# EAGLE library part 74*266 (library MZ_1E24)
Quadruple EXCLUSIVE-NOR (XNOR), open-collector
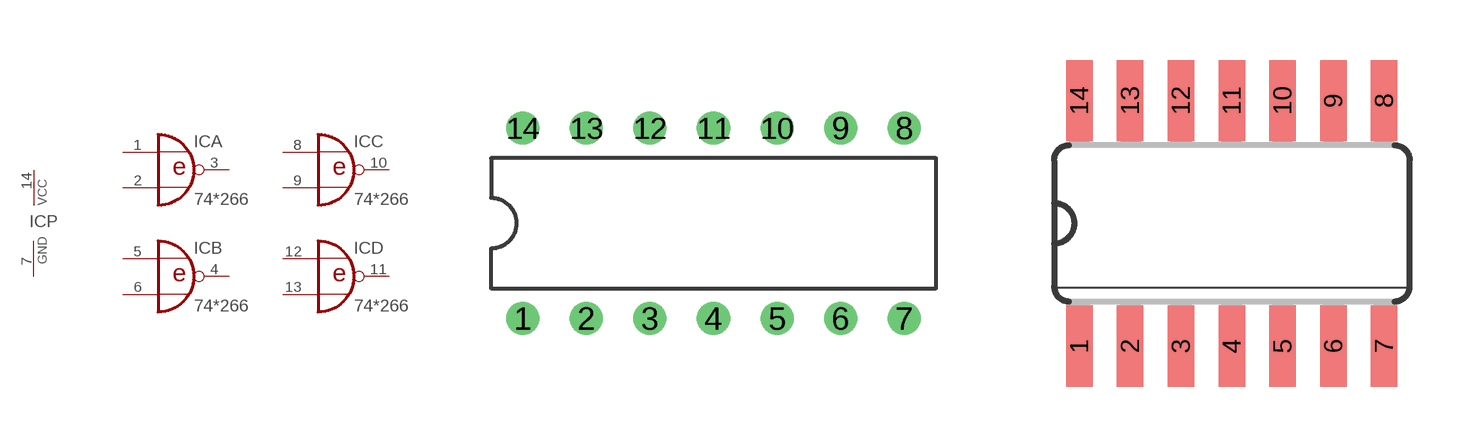
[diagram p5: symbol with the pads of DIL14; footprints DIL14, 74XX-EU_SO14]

Designator prefix IC; gates A=EU_74266 B=EU_74266 C=EU_74266 D=EU_74266 P=EU_PWRN

## 74266  [DIL14]
1  A:I0  in
2  A:I1  in
3  A:O  oc
4  B:O  oc
5  B:I0  in
6  B:I1  in
7  P:GND  pwr
8  C:I0  in
9  C:I1  in
10  C:O  oc
11  D:O  oc
12  D:I0  in
13  D:I1  in
14  P:VCC  pwr

## 74266D, 74HC266D  [74XX-EU_SO14]
Pads as for DIL14

## 74266FK, 74HC266FK, 74LS266FK  [74XX-EU_LCC20]
2  A:I0  in
3  A:I1  in
4  A:O  oc
6  B:O  oc
8  B:I0  in
9  B:I1  in
10  P:GND  pwr
12  C:I0  in
13  C:I1  in
14  C:O  oc
16  D:O  oc
18  D:I0  in
19  D:I1  in
20  P:VCC  pwr

## Footprint DIL14 (pad centres in mm)
Dual In Line Package
drill 0.813 round: 1 -7.62,-3.81; 2 -5.08,-3.81; 3 -2.54,-3.81; 4 0,-3.81; 5 2.54,-3.81; 6 5.08,-3.81; 7 7.62,-3.81; 8 7.62,3.81; 9 5.08,3.81; 10 2.54,3.81; 11 0,3.81; 12 -2.54,3.81; 13 -5.08,3.81; 14 -7.62,3.81

## Footprint 74XX-EU_SO14 (pad centres in mm)
Small Outline package 150 mil
smd 0.66 x 2.032: 1 -3.81,-3.073; 2 -2.54,-3.073; 3 -1.27,-3.073; 4 0,-3.073; 5 1.27,-3.073; 6 2.54,-3.073; 7 3.81,-3.073; 8 3.81,3.073; 9 2.54,3.073; 10 1.27,3.073; 11 0,3.073; 12 -1.27,3.073; 13 -2.54,3.073; 14 -3.81,3.073

## Footprint 74XX-EU_LCC20 (pad centres in mm)
Leadless Chip Carrier Ceramic Package
smd 0.8 x 3.4: 1 0,3.8
smd 0.8 x 2: 2 -1.27,4.5; 3 -2.54,4.5; 9 -2.54,-4.5; 10 -1.27,-4.5; 11 0,-4.5; 12 1.27,-4.5; 13 2.54,-4.5; 19 2.54,4.5; 20 1.27,4.5
smd 2 x 0.8: 4 -4.5,2.54; 5 -4.5,1.27; 6 -4.5,0; 7 -4.5,-1.27; 8 -4.5,-2.54; 14 4.5,-2.54; 15 4.5,-1.27; 16 4.5,0; 17 4.5,1.27; 18 4.5,2.54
